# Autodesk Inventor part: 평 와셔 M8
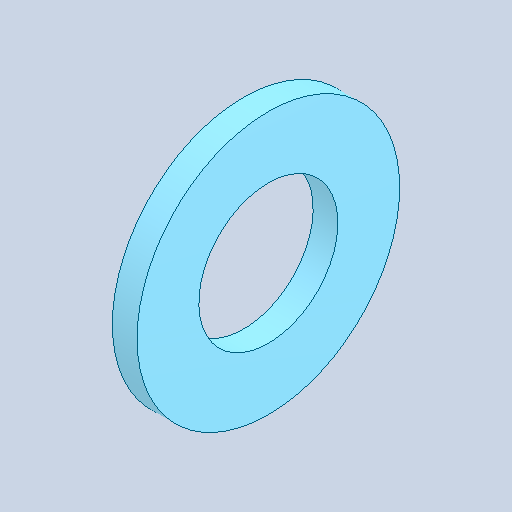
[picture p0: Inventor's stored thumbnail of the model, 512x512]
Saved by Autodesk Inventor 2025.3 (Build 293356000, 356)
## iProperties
Created: 2025-10
Part Number: 평 와셔 M8
Material: 강철, 연강
Description: 평면 와셔
Document SubType Name: Modeling
Designer: USER
Density: 7.85 g/cm^3
Appearance: 기본값
Author: jhkim
Sending System: Autodesk Inventor 2026
Preprocessor: ST-DEVELOPER v20.1
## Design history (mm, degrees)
feature "Solid1"
node "솔리드1"
